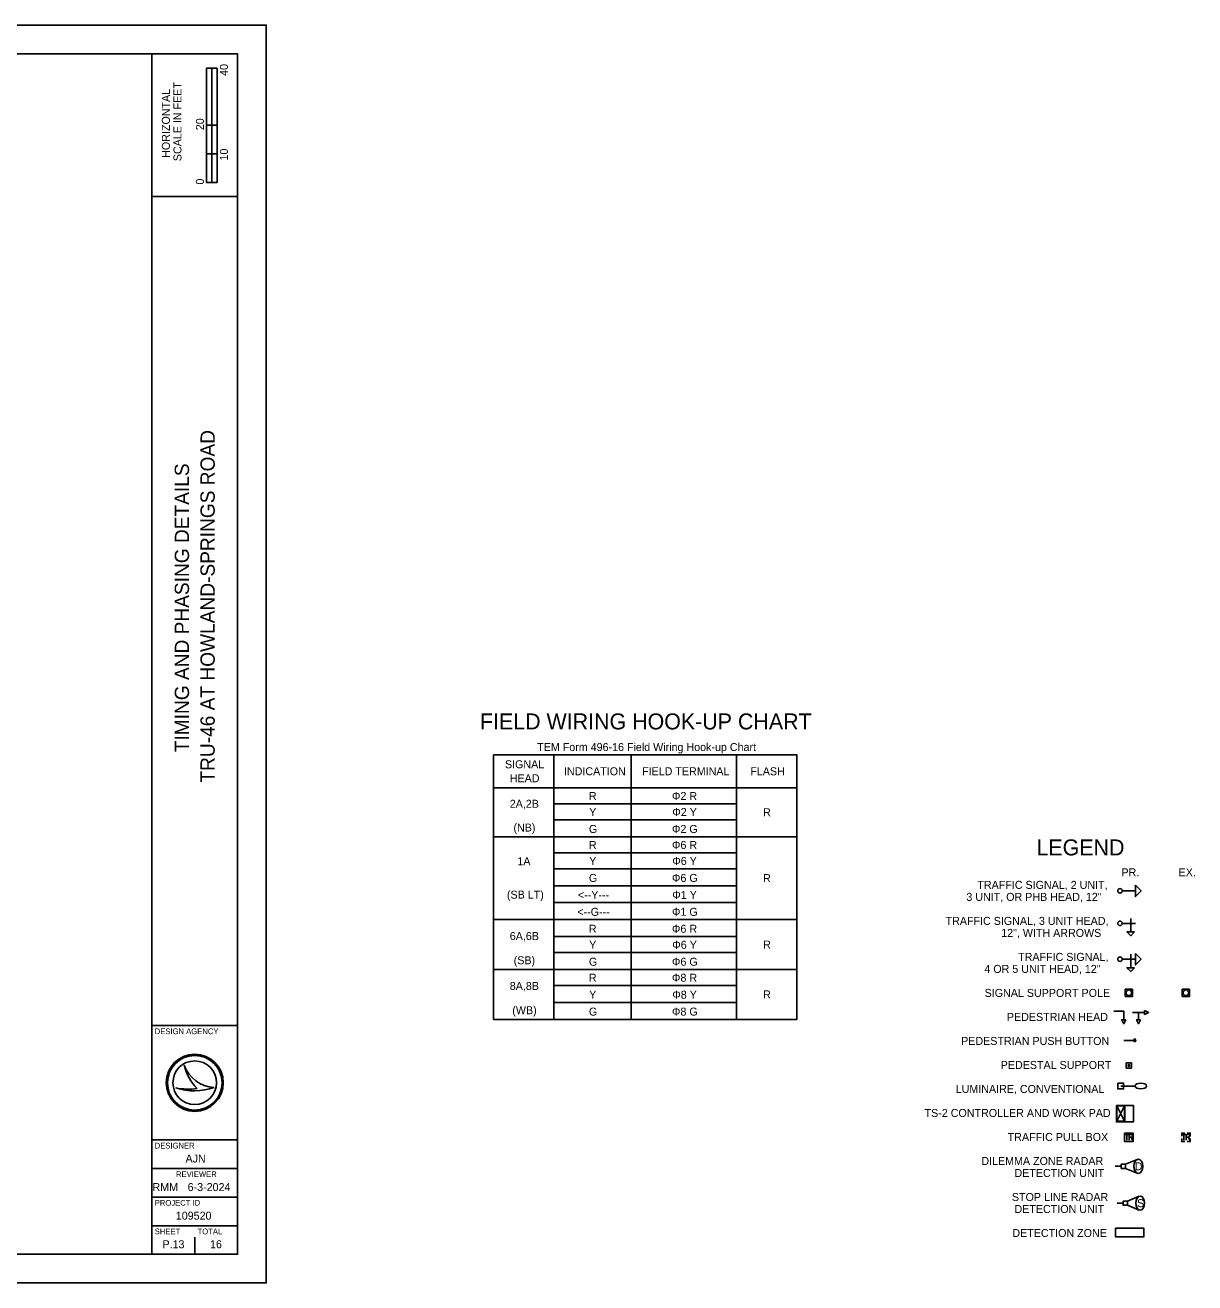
# Model space of a CAD drawing. Extents: x -513 to 1005, y -278 to 699.
# Drawn here: x 595.7 to 1005, y 0 to 440 of the extents above; entities that cross this region are included whole.
import ezdxf

# ---------------------------------------------------------------- set-up
doc = ezdxf.new("R2010")
doc.units = 0
for name, color, linetype in [('_CIVIL_CONSTRUCTION', 7, 'Continuous'), ('Default', 7, 'Continuous'), ('HY_X_Wetland_Area', 7, 'Continuous'), ('HY_X_Wetland_Cells', 7, 'Continuous'), ('PM_P_CL_Double_Solid', 7, 'Continuous'), ('PM_X_CL_Pass_Proh_Lt', 7, 'Continuous'), ('PV_X_Driveway', 7, 'Continuous'), ('SC_Scratch1', 7, 'Continuous'), ('SG_P_Controllers', 7, 'Continuous'), ('SG_P_Detection', 7, 'Continuous'), ('SG_P_Heads', 7, 'Continuous'), ('SG_P_Poles', 7, 'Continuous'), ('SG_P_PullBox', 7, 'Continuous'), ('SH_Text', 7, 'Continuous'), ('UT_X_Overhead_Combined', 7, 'Continuous'), ('UT_X_Telecom', 7, 'Continuous'), ('Wetlands_rev20191008', 7, 'Continuous')]:
    doc.layers.add(name, color=color, linetype=linetype)

msp = doc.modelspace()

# ---------------------------------------------------------------- linework, layer by layer
at = {"layer": '_CIVIL_CONSTRUCTION'}
msp.add_line((981.87, 50.91), (981.87, 50.91), dxfattribs=at)
msp.add_lwpolyline([(980.37, 52.41), (983.37, 52.41), (983.37, 49.41), (980.37, 49.41)], close=True, dxfattribs=at)
for points in [[(980.51, 51.91), (981.76, 51.91)], [(981.14, 51.91), (981.14, 49.91)], [(981.98, 49.91), (981.98, 51.91), (982.74, 51.91), (982.81, 51.89), (982.92, 51.86), (982.97, 51.83), (983.02, 51.8), (983.08, 51.72), (983.13, 51.64), (983.16, 51.51), (983.16, 51.33), (983.14, 51.26), (983.11, 51.17), (983.05, 51.06), (982.99, 51.01), (982.94, 50.98), (982.91, 50.96), (982.86, 50.95), (982.72, 50.93), (981.98, 50.93)], [(982.72, 50.93), (983.16, 49.91)]]:
    msp.add_lwpolyline(points, dxfattribs=at)
at = {"layer": 'Default'}
msp.add_lwpolyline([(759.6, 184.73), (865.67, 184.73), (865.67, 92.17), (759.6, 92.17)], close=True, dxfattribs=at)
at = {"layer": 'HY_X_Wetland_Area'}
msp.add_lwpolyline([(980.97, 75.14), (982.77, 75.14), (982.77, 76.94), (980.97, 76.94)], close=True, dxfattribs=at)
msp.add_circle((981.87, 76.04), 0.3, dxfattribs=at)
at = {"layer": 'HY_X_Wetland_Cells'}
msp.add_line((1001.86, 50.91), (1001.86, 50.91), dxfattribs=at)
for points in [[(1001.46, 52.41), (1000.36, 52.41), (1000.36, 51.31)], [(1000.36, 50.51), (1000.36, 49.41), (1001.46, 49.41)], [(1000.5, 51.91), (1001.75, 51.91)], [(1001.13, 51.91), (1001.13, 49.91)], [(1001.97, 49.91), (1001.97, 51.91), (1002.73, 51.91), (1002.8, 51.89), (1002.91, 51.86), (1002.96, 51.83), (1003.01, 51.8), (1003.07, 51.72), (1003.12, 51.64), (1003.15, 51.51), (1003.15, 51.33), (1003.14, 51.26), (1003.1, 51.17), (1003.04, 51.06), (1002.98, 51.01), (1002.93, 50.98), (1002.9, 50.96), (1002.85, 50.95), (1002.71, 50.93), (1001.97, 50.93)], [(1003.36, 51.31), (1003.36, 52.41), (1002.26, 52.41)], [(1002.26, 49.41), (1003.36, 49.41), (1003.36, 50.51)], [(1002.71, 50.93), (1003.15, 49.91)]]:
    msp.add_lwpolyline(points, dxfattribs=at)
at = {"layer": 'PM_X_CL_Pass_Proh_Lt'}
for p, q in [((977.66, 56.53), (980.3, 61.9)), ((980.3, 56.53), (977.66, 61.9))]:
    msp.add_line(p, q, dxfattribs=at)
msp.add_lwpolyline([(977.49, 62.07), (980.49, 62.07), (983.49, 62.07), (983.49, 56.32), (977.49, 56.32), (977.49, 56.32)], close=True, dxfattribs=at)
for points in [[(977.49, 56.32), (980.49, 56.32), (980.49, 62.07)], [(980.3, 56.53), (980.3, 61.9), (977.66, 61.9), (977.66, 56.53), (980.3, 56.53)]]:
    msp.add_lwpolyline(points, dxfattribs=at)
at = {"layer": 'SC_Scratch1'}
msp.add_lwpolyline([(640, 10), (640, 430), (30, 430), (30, 10)], close=True, dxfattribs=at)
at = {"layer": 'SG_P_Controllers'}
msp.add_lwpolyline([(980.62, 100.22), (983.12, 100.22), (983.12, 102.72), (980.62, 102.72)], close=True, dxfattribs=at)
msp.add_circle((981.87, 101.47), 1, dxfattribs=at)
at = {"layer": 'SG_P_Detection'}
msp.add_lwpolyline([(0, 0), (680, 0), (680, 440), (0, 440)], close=True, dxfattribs=at)
at = {"layer": 'SG_P_Heads'}
for p, q in [((640, 10), (640, 430)), ((640, 380), (670, 380)), ((640, 90), (670, 90)), ((640, 50), (670, 50)), ((640, 40), (670, 40)), ((640, 30), (670, 30)), ((640, 20), (670, 20))]:
    msp.add_line(p, q, dxfattribs=at)
msp.add_lwpolyline([(30, 430), (670, 430), (670, 10), (30, 10)], close=True, dxfattribs=at)
at = {"layer": 'SG_P_Poles'}
for p, q in [((759.6, 184.73), (865.67, 184.73)), ((759.6, 184.73), (759.6, 92.17)), ((780.69, 184.73), (780.69, 92.17)), ((807.7, 184.73), (807.7, 92.17)), ((844.59, 184.73), (844.59, 92.17)), ((865.67, 184.73), (865.67, 92.17)), ((759.6, 173.2), (865.67, 173.2)), ((780.69, 167.6), (844.59, 167.6)), ((780.69, 162), (844.59, 162)), ((759.6, 156.07), (865.67, 156.07)), ((780.69, 150.47), (844.59, 150.47)), ((780.69, 144.87), (844.59, 144.87)), ((780.69, 138.94), (844.59, 138.94)), ((780.69, 133.02), (844.59, 133.02)), ((780.69, 133.02), (807.7, 133.02)), ((759.6, 127.09), (865.67, 127.09)), ((780.69, 121.16), (844.59, 121.16)), ((780.69, 115.56), (844.59, 115.56)), ((759.6, 109.63), (865.67, 109.63)), ((780.69, 104.03), (844.59, 104.03)), ((780.69, 98.1), (844.59, 98.1)), ((759.6, 92.17), (844.59, 92.17)), ((844.59, 92.17), (865.67, 92.17))]:
    msp.add_line(p, q, dxfattribs=at)
at = {"layer": 'SG_P_PullBox'}
for p, q in [((659.13, 385), (659.13, 425)), ((662.88, 425), (659.13, 425)), ((659.13, 405), (659.13, 425)), ((659.13, 425), (661, 425)), ((661, 425), (661.02, 425)), ((661.02, 425), (661.02, 405)), ((662.88, 425), (662.88, 385)), ((661.02, 405), (659.13, 405)), ((662.87, 405), (661, 405)), ((661, 405), (661, 395)), ((662.87, 395), (662.87, 405)), ((661, 395), (659.13, 395)), ((659.13, 395), (659.13, 385)), ((661, 385), (661, 395)), ((661, 395), (662.87, 395)), ((662.88, 385), (659.13, 385)), ((659.13, 385), (661, 385)), ((651.35, 76.19), (651.35, 76.19)), ((648.34, 68.19), (648.34, 68.19)), ((655, 70), (655, 70)), ((661.75, 68.37), (661.75, 68.37)), ((647.5, 13.5), (647.5, 13.5)), ((655, 10), (655, 16))]:
    msp.add_line(p, q, dxfattribs=at)
for radius in [10, 9.54, 9.54, 7.64]:
    msp.add_circle((655, 70), radius, dxfattribs=at)
for centre, radius, start, end in [((662.32, 79.95), 11.6, 198.9257, 198.9319), ((666.93, 79.4), 15.91, 191.6379, 191.6421), ((662.32, 79.95), 11.6, 198.9319, 267.1657), ((666.93, 79.4), 15.91, 191.6421, 226.0947), ((654.79, 87.4), 20.26, 251.4576, 290.0832), ((652.96, 93.09), 25.32, 259.4964, 259.4995), ((654.79, 87.4), 20.26, 251.4527, 251.4576), ((652.96, 93.09), 25.32, 259.4995, 276.6672)]:
    msp.add_arc(centre, radius, start, end, dxfattribs=at)
at = {"layer": 'SH_Text'}
msp.add_line((979.04, 68.86), (984.04, 68.86), dxfattribs=at)
msp.add_lwpolyline([(978.04, 69.86), (980.04, 69.86), (980.04, 67.86), (978.04, 67.86)], close=True, dxfattribs=at)
msp.add_ellipse((986.04, 68.86), major_axis=(2, 0), ratio=0.5, dxfattribs=at)
at = {"layer": 'UT_X_Overhead_Combined'}
msp.add_lwpolyline([(1000.58, 100.22), (1003.08, 100.22), (1003.08, 102.72), (1000.58, 102.72)], close=True, dxfattribs=at)
msp.add_circle((1001.83, 101.47), 1, dxfattribs=at)
at = {"layer": 'UT_X_Telecom'}
for p, q in [((979.57, 137.13), (984.17, 137.13)), ((979.57, 125.76), (984.17, 125.76)), ((982.55, 127.48), (982.55, 122.78)), ((982.55, 114.93), (982.55, 110.23)), ((979.57, 113.22), (984.17, 113.22)), ((975.4, 95.03), (975.4, 95.03)), ((981.98, 94.63), (981.98, 94.63)), ((983.18, 94.63), (987.38, 94.63)), ((985.28, 94.63), (985.28, 92.03))]:
    msp.add_line(p, q, dxfattribs=at)
for points in [[(984.16, 139.13), (986.16, 137.13), (984.16, 135.13)], [(983.88, 122.79), (982.55, 121.45), (981.21, 122.79)], [(984.16, 115.22), (986.16, 113.22), (984.16, 111.22)], [(983.86, 110.24), (982.53, 108.91), (981.2, 110.24)], [(987.38, 95.33), (987.38, 93.93), (988.78, 94.63)], [(980.8, 92.03), (979.4, 92.03), (980.1, 90.63)], [(985.98, 92.03), (984.58, 92.03), (985.28, 90.63)]]:
    msp.add_lwpolyline(points, close=True, dxfattribs=at)
msp.add_lwpolyline([(976.6, 95.03), (980.1, 95.03), (980.1, 92.03)], dxfattribs=at)
for centre in [(978.77, 137.13), (978.77, 125.76), (978.77, 113.22)]:
    msp.add_circle(centre, 0.8, dxfattribs=at)
at = {"layer": 'Wetlands_rev20191008'}
for p, q in [((980.12, 84.84), (983.72, 84.84)), ((983.72, 85.4), (983.72, 84.28)), ((977.06, 40.77), (979.18, 40.77)), ((980.68, 41.52), (984.8, 43.17)), ((984.8, 43.17), (980.68, 41.52)), ((980.68, 41.52), (980.68, 40.02)), ((980.68, 40.02), (980.68, 41.52)), ((980.68, 40.02), (984.79, 38.36)), ((980.68, 40.02), (984.79, 38.36)), ((977.72, 27.87), (979.84, 27.87)), ((981.34, 28.62), (985.45, 30.27)), ((985.45, 30.27), (981.34, 28.62)), ((981.34, 28.62), (981.34, 27.12)), ((981.34, 27.12), (985.45, 25.46)), ((981.34, 27.12), (985.45, 25.46))]:
    msp.add_line(p, q, dxfattribs=at)
for points in [[(979.18, 41.52), (979.18, 40.02), (980.68, 40.02), (980.68, 41.52)], [(979.84, 28.62), (979.84, 27.12), (981.34, 27.12), (981.34, 28.62)], [(977.16, 19.1), (987.16, 19.1), (987.16, 16.1), (977.16, 16.1)]]:
    msp.add_lwpolyline(points, close=True, dxfattribs=at)
for points in [[(980.68, 41.52), (979.18, 41.52), (979.18, 40.02), (980.68, 40.02)], [(979.84, 28.62), (979.84, 27.12), (981.34, 27.12), (981.34, 28.62), (979.84, 28.62)]]:
    msp.add_lwpolyline(points, dxfattribs=at)
msp.add_arc((983.72, 84.84), 0.56, 270.0002, 89.9998, dxfattribs=at)
for centre in [(985.17, 40.77), (985.83, 27.87)]:
    msp.add_ellipse(centre, major_axis=(0, -2.48), ratio=0.621318, dxfattribs=at)
for centre in [(985.17, 40.77), (985.83, 27.87)]:
    msp.add_ellipse(centre, major_axis=(0, -2.48), ratio=0.621318, start_param=3.386213, end_param=6.038231, dxfattribs=at)

# ---------------------------------------------------------------- texts
at = {"layer": 'Default'}
msp.add_text('FIELD WIRING HOOK-UP CHART', height=5.6, dxfattribs=at).set_placement((754.8, 193.61))
at = {"layer": 'PM_P_CL_Double_Solid'}
msp.add_text('LEGEND', height=5.6, dxfattribs=at).set_placement((949.54, 149.54))
at = {"layer": 'PV_X_Driveway'}
for s, p in [('3 UNIT, OR PHB HEAD, 12"', (925.01, 133.63)), ('TRAFFIC SIGNAL, 2 UNIT,', (928.86, 137.83)), ('TRAFFIC SIGNAL, 3 UNIT HEAD,', (917.74, 125.23)), ('12", WITH ARROWS', (937.2, 121.03)), ('TRAFFIC SIGNAL, ', (943.12, 112.63)), ('4 OR 5 UNIT HEAD, 12"', (931.31, 108.43)), ('SIGNAL SUPPORT POLE', (931.4, 100.03)), ('PEDESTRIAN HEAD', (939.19, 91.63)), ('PEDESTRIAN PUSH BUTTON', (923.18, 83.23)), ('PEDESTAL SUPPORT', (937.03, 74.83)), ('LUMINAIRE, CONVENTIONAL', (921.27, 66.43)), ('TS-2 CONTROLLER AND WORK PAD', (910.39, 58.03)), ('TRAFFIC PULL BOX', (939.47, 49.63)), ('DILEMMA ZONE RADAR', (930.25, 41.23)), ('DETECTION UNIT', (941.84, 37.03)), ('STOP LINE RADAR', (940.94, 28.63)), ('DETECTION UNIT', (941.84, 24.43)), ('DETECTION ZONE', (941.1, 16.03))]:
    msp.add_text(s, height=2.8, dxfattribs=at).set_placement(p)
at = {"layer": 'SG_P_Poles'}
for s, p in [('TEM Form 496-16 Field Wiring Hook-up Chart', (774.83, 186.05)), ('SIGNAL ', (763.55, 180.02)), ('INDICATION', (784.2, 177.57)), ('FLASH', (849.4, 177.57)), ('HEAD', (765.24, 175.12)), ('FIELD TERMINAL', (811.53, 177.57)), ('R', (792.93, 168.92)), ('Φ2 R', (821.97, 168.92)), ('2A,2B', (765.24, 166.2)), ('Y', (793.02, 163.32)), ('Φ2 Y', (822.09, 163.32)), ('R', (853.87, 163.24)), ('(NB)', (766.52, 157.89)), ('G', (792.93, 157.39)), ('Φ2 G', (821.97, 157.39)), ('R', (792.93, 151.79)), ('Φ6 R', (821.97, 151.79)), ('1A', (767.9, 146.11)), ('Y', (793.02, 146.19)), ('Φ6 Y', (822.09, 146.19)), ('G', (792.93, 140.26)), ('Φ6 G', (821.97, 140.26)), ('R', (853.87, 140.18)), ('PR.', (979.28, 142.22)), ('EX.', (999.27, 142.22)), ('(SB LT)', (764.24, 134.42)), ('<--Y---', (789.07, 134.33)), ('Φ1 Y', (822.09, 134.33)), ('<--G---', (788.88, 128.4)), ('Φ1 G', (821.97, 128.4)), ('R', (792.93, 122.47)), ('Φ6 R', (821.97, 122.47)), ('6A,6B', (765.24, 119.92)), ('Y', (793.02, 116.87)), ('Φ6 Y', (822.09, 116.87)), ('R', (853.87, 116.96)), ('(SB)', (766.61, 111.44)), ('G', (792.93, 110.94)), ('Φ6 G', (821.97, 110.94)), ('R', (792.93, 105.34)), ('Φ8 R', (821.97, 105.34)), ('8A,8B', (765.24, 102.46)), ('Y', (793.02, 99.42)), ('Φ8 Y', (822.09, 99.42)), ('R', (853.87, 99.5)), ('(WB)', (766.13, 93.98)), ('G', (792.93, 93.49)), ('Φ8 G', (821.97, 93.49))]:
    msp.add_text(s, height=2.8, dxfattribs=at).set_placement(p)
at = {"layer": 'SG_P_PullBox'}
for s, height, p in [('40', 2.8, (666.61, 422.25)), ('SCALE IN FEET', 2.8, (650.35, 392.41)), ('HORIZONTAL', 2.8, (646.3, 393.58)), ('20', 2.8, (658.21, 403.25)), ('10', 2.8, (666.61, 392.65)), ('0', 2.8, (658.21, 384.23)), ('TRU-46 AT HOWLAND-SPRINGS ROAD', 5, (662, 175.02)), ('TIMING AND PHASING DETAILS', 5, (653, 185.63))]:
    msp.add_text(s, height=height, rotation=90, dxfattribs=at).set_placement(p)
for s, height, p in [('DESIGN AGENCY', 2, (641, 87)), ('DESIGNER', 2, (641, 47)), ('AJN', 2.8, (651.76, 42.1)), ('REVIEWER', 2, (648.44, 37)), ('RMM', 2.8, (640.22, 32.1)), ('6-3-2024', 2.8, (652.51, 32.1)), ('PROJECT ID', 2, (641, 27)), ('109520', 2.8, (648.37, 22.1)), ('SHEET', 2, (641, 17)), ('TOTAL', 2, (656, 17)), ('P.13', 2.8, (643.7, 12.1)), ('16', 2.8, (660.35, 12.1))]:
    msp.add_text(s, height=height, dxfattribs=at).set_placement(p)
at = {"layer": 'Wetlands_rev20191008'}
for s, p in [('D', (983.91, 39.37)), ('S', (984.73, 26.47))]:
    msp.add_text(s, height=2.8, dxfattribs=at).set_placement(p)

doc.saveas('drawing.dxf')
